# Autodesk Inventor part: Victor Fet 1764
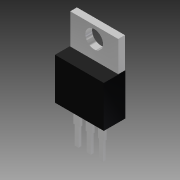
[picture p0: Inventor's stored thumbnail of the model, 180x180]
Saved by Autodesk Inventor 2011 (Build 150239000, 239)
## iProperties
Shininess: 64.0
Length Units: 11272
Angle Units: 11279
Time Units: 11290
Mass Units: 11286
Length Display Precision: 3
Angle Display Precision: 2
Compacted: True
Part Number: Victor Fet 1764
Document SubType Name: Modeling
Created: 2007-01
Designer: uidk0133
Density: 1 g/cm^3
Density: 0.0
Volumn: 0.0
Area: 0.0
PropertySet Name: Model Information
Control State: 0
Master: False
Checked Out: False
Author: uidk0133
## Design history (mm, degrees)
sketch "Sketch1"
  geometry: L1 (-5.08, 8.636)-(5.08, 8.636); L2 (5.08, 8.636)-(5.08, 0); L3 (5.08, 0)-(-5.08, 0); L4 (-5.08, 0)-(-5.08, 8.636); 2 further points
  constraints: 8 end point, 2 parallel, 1 coincident, 1 horizontal, 1 midpoint, 1 perpendicular, 1 other
  dimensions: "d0" = 10.16 distance of L1.start L1.end; "d1" = 8.636 distance of L1.end L2.end
extrude "Extrusion1" new body sketch "Sketch1" distance "d2" = 4.4704; taper "d3" = 0 deg
sketch "Sketch2"
  geometry: L1 (0.089, -1.397)-(10.071, -1.397); L2 (10.071, -1.397)-(10.071, 0); L3 (10.071, 0)-(0.089, 0); L4 (0.089, 0)-(0.089, -1.397); L5 (0, 0)-(10.16, 0) reference; 1 further point
  constraints: 8 end point, 2 midpoint, 2 parallel, 1 horizontal, 1 perpendicular
  dimensions: "d7" = 1.397 distance of L3.end L1.start; "d8" = 9.9822 distance of L1.start L1.end
extrude "Extrusion2" join sketch "Sketch2" distance "d5" = 6.35; taper "d6" = 0 deg
sketch "Sketch3"
  geometry: L1 (9.982, 6.35)-(0, 6.35) reference; L2 (9.982, 0)-(9.982, 6.35) reference; L3 (4.991, 6.35)-(4.991, 1.588); 1 further point
  constraints: 2 end point, 1 midpoint, 1 parallel, 1 point on line
  dimensions: "d9" = 2.54 distance from line of L1 point (4.991, 3.81)
hole "Hole1" sketch "Sketch3" at (4.991, 3.81) diameter "d10" = 3.683; stored, may be unused: countersink angle "d14" = 82 deg, drill point angle "d16" = 118 deg; dims "d11" = 12.7, "d12" = 9.525, "d13" = 6.35, "d15" = 19.05
sketch "Sketch4"
  geometry: L1 (0, 0)-(0, 4.47) reference; L2 (10.16, 0)-(10.16, 4.47) reference; L3 (0, 2.235)-(10.16, 2.235); L4 (1.905, 2.527)-(3.175, 2.527); L5 (3.175, 2.527)-(3.175, 1.943); L6 (3.175, 1.943)-(1.905, 1.943); L7 (1.905, 1.943)-(1.905, 2.527); 1 further point
  constraints: 10 end point, 3 midpoint, 2 parallel, 1 horizontal, 1 perpendicular, 1 point on line
  dimensions: "d17" = 0.5842 distance of L4.end L5.end; "d18" = 1.27 distance of L5.end L6.end; "d19" = 1.905 distance from line of L1 L4.start
extrude "Extrusion3" join sketch "Sketch4" distance "d20" = 3.81; taper "d21" = 0 deg
sketch "Sketch5"
  geometry: L1 (1.905, 2.527)-(3.175, 2.527) reference; L2 (3.175, 1.943)-(1.905, 1.943) reference; L3 (2.134, 2.527)-(2.946, 2.527); L4 (2.946, 2.527)-(2.946, 1.943); L5 (2.946, 1.943)-(2.134, 1.943); L6 (2.134, 1.943)-(2.134, 2.527); 1 further point
  constraints: 8 end point, 2 midpoint, 2 parallel, 2 point on line, 1 horizontal, 1 perpendicular
  dimensions: "d22" = 0.8128 distance between parallel lines of L4 L6
extrude "Extrusion4" join sketch "Sketch5" distance "d23" = 3.81; taper "d24" = 0 deg
pattern_linear "Rectangular Pattern1" dims "d27" = 2.54
body "Solid1"
